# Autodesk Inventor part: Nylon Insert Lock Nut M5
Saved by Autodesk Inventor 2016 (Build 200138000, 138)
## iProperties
Created: 2015-11
Part Number: Nylon Insert Lock Nut M5
Material: Generic
Document SubType Name: Modeling
Designer: John
Density: 1 g/cm^3
Appearance: Default
Author: John
Revision Number: ANY
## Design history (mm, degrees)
feature "Cut-Extrude1"
body "Solid1"
